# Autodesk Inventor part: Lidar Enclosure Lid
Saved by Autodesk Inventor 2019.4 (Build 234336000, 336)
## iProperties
Created: 2020-05
Part Number: Lidar Enclosure Lid
Material: Generic
Document SubType Name: Modeling
Designer: Administrator
Density: 1 g/cm^3
Appearance: Default
Title: Lidar Enclosure Lid
Author: Administrator
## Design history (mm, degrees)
feature "Body1"
body "Solid1"
